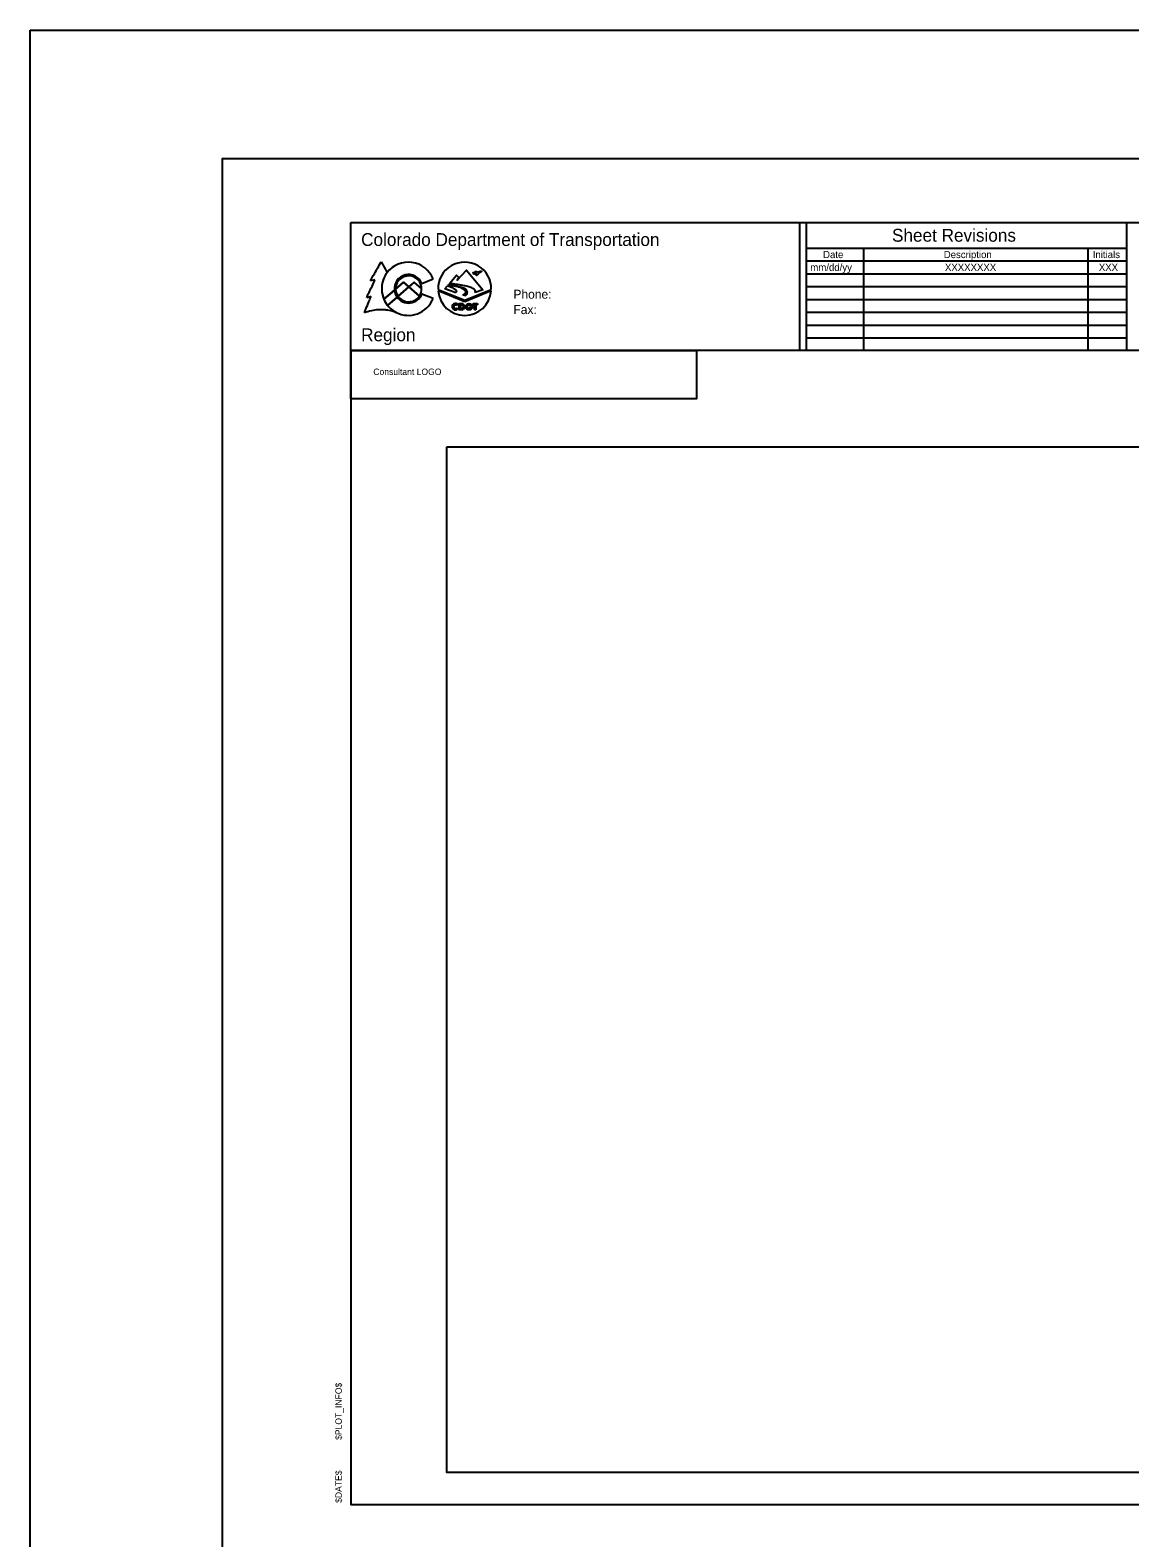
# Model space of a CAD drawing. Extents: x 0 to 3, y 0 to 2.
# Drawn here: x 0 to 0.715, y 1.02 to 2 of the extents above; entities that cross this region are included whole.
import ezdxf

# ---------------------------------------------------------------- set-up
doc = ezdxf.new("R2010")
doc.units = 0
for name, color, linetype in [('DRAFT_Information-No Plot', 7, 'Continuous'), ('SHEET_Lines', 7, 'Continuous'), ('SHEET_North Arrow', 7, 'Continuous'), ('SHEET_Plot Boundary', 7, 'Continuous'), ('SHEET_Text-Border Info', 7, 'Continuous')]:
    doc.layers.add(name, color=color, linetype=linetype)

msp = doc.modelspace()

# ---------------------------------------------------------------- linework, layer by layer
at = {"layer": 'DRAFT_Information-No Plot'}
msp.add_line((0.20833, 1.79167), (0.20833, 1.79167), dxfattribs=at)
msp.add_lwpolyline([(0.27083, 1.72917), (1.4375, 1.72917), (1.4375, 1.0625), (0.27083, 1.0625)], close=True, dxfattribs=at)
at = {"layer": 'SHEET_Lines'}
for p, q in [((0.20833, 1.79167), (0.20833, 1.875)), ((0.20833, 1.875), (1.5, 1.875)), ((0.5, 1.875), (0.5, 1.79167)), ((0.50417, 1.875), (0.50417, 1.79167)), ((0.7125, 1.875), (0.7125, 1.79167)), ((0.50417, 1.85833), (0.7125, 1.85833)), ((0.54167, 1.79167), (0.54167, 1.85833)), ((0.6875, 1.79167), (0.6875, 1.85833)), ((0.50417, 1.85), (0.7125, 1.85)), ((0.50417, 1.84167), (0.7125, 1.84167)), ((0.50417, 1.83333), (0.7125, 1.83333)), ((0.50417, 1.825), (0.7125, 1.825)), ((0.50417, 1.81667), (0.7125, 1.81667)), ((0.50417, 1.80833), (0.7125, 1.80833)), ((0.50417, 1.8), (0.7125, 1.8))]:
    msp.add_line(p, q, dxfattribs=at)
for points in [[(2.95833, 0.08333), (0.125, 0.08333), (0.125, 1.91667), (2.95833, 1.91667)], [(0.20833, 1.79167), (0.43293, 1.79167), (0.43293, 1.76025), (0.20833, 1.76025)]]:
    msp.add_lwpolyline(points, close=True, dxfattribs=at)
msp.add_lwpolyline([(1.1375, 1.79167), (0.20833, 1.79167), (0.20833, 1.04167), (1.5, 1.04167), (1.5, 1.79167), (1.275, 1.79167)], dxfattribs=at)
at = {"layer": 'SHEET_Plot Boundary'}
for p, q in [((0.22801, 1.8493), (0.232, 1.84245)), ((0.22395, 1.83769), (0.22115, 1.83706)), ((0.24264, 1.83614), (0.23747, 1.83166)), ((0.23747, 1.83161), (0.24264, 1.83609)), ((0.2461, 1.83313), (0.23903, 1.827)), ((0.23903, 1.827), (0.2461, 1.83313)), ((0.2461, 1.83313), (0.24264, 1.83614)), ((0.24264, 1.83609), (0.2461, 1.83308)), ((0.24955, 1.83613), (0.2461, 1.83313)), ((0.2461, 1.83308), (0.24955, 1.83608)), ((0.25295, 1.82719), (0.2461, 1.83313)), ((0.2461, 1.83313), (0.25295, 1.82719)), ((0.25438, 1.83194), (0.24955, 1.83613)), ((0.24955, 1.83608), (0.25438, 1.83189)), ((0.2545, 1.83542), (0.26182, 1.83834)), ((0.26939, 1.83182), (0.27121, 1.8339)), ((0.27167, 1.83442), (0.27189, 1.83467)), ((0.29036, 1.84177), (0.28894, 1.84145)), ((0.22151, 1.82697), (0.21867, 1.82609)), ((0.22986, 1.82505), (0.23669, 1.83098)), ((0.23669, 1.83098), (0.22986, 1.82505)), ((0.2384, 1.82645), (0.23224, 1.8211)), ((0.23224, 1.8211), (0.2384, 1.82645)), ((0.26182, 1.82552), (0.25453, 1.82842)), ((0.26506, 1.83148), (0.28236, 1.82442)), ((0.28236, 1.82343), (0.26511, 1.83046)), ((0.2755, 1.82967), (0.26939, 1.83182)), ((0.28142, 1.82766), (0.28106, 1.82781)), ((0.28255, 1.82728), (0.28215, 1.82746)), ((0.28236, 1.82442), (0.29966, 1.83148)), ((0.2996, 1.83046), (0.28236, 1.82343)), ((0.27715, 1.81944), (0.27787, 1.81876)), ((0.27788, 1.82166), (0.27716, 1.82099)), ((0.28784, 1.82135), (0.28784, 1.82223)), ((0.28784, 1.82223), (0.29066, 1.82223)), ((0.2888, 1.82135), (0.28784, 1.82135)), ((0.2888, 1.81812), (0.2888, 1.82135)), ((0.2897, 1.81812), (0.2888, 1.81812)), ((0.29066, 1.82135), (0.2897, 1.82135)), ((0.2897, 1.82135), (0.2897, 1.81812)), ((0.29066, 1.82223), (0.29066, 1.82135))]:
    msp.add_line(p, q, dxfattribs=at)
msp.add_lwpolyline([(0, 2), (3, 2), (3, 0), (0, 0)], close=True, dxfattribs=at)
for points in [[(0.27243, 1.83528), (0.27713, 1.84065), (0.27848, 1.83924), (0.2775, 1.8375), (0.28344, 1.84402), (0.29416, 1.8313), (0.28907, 1.82956)], [(0.2805, 1.81812), (0.27873, 1.81812), (0.27873, 1.82223), (0.2805, 1.82223)], [(0.28027, 1.82136), (0.27966, 1.82136), (0.27966, 1.81901), (0.28027, 1.81901)]]:
    msp.add_lwpolyline(points, dxfattribs=at)
for radius in [0.00212, 0.00114]:
    msp.add_circle((0.28516, 1.82022), radius, dxfattribs=at)
for centre, radius, start, end in [((0.24574, 1.83192), 0.01731, 21.75871, 203.38863), ((0.24576, 1.83193), 0.01732, 142.59022, 242.67381), ((0.28236, 1.83192), 0.01731, 358.51701, 181.48299), ((0.24592, 1.83189), 0.00928, 22.36058, 185.62032), ((0.24592, 1.83184), 0.00845, 0.35858, 181.56098), ((0.24574, 1.83192), 0.01731, 203.38863, 242.71912), ((0.24592, 1.83189), 0.00928, 185.62032, 215.87253), ((0.24592, 1.83189), 0.00845, 181.56098, 215.37659), ((0.24574, 1.83192), 0.01731, 242.71912, 338.26838), ((0.24592, 1.83189), 0.00928, 215.87253, 338.04863), ((0.24592, 1.83189), 0.00845, 215.37659, 326.23275), ((0.24592, 1.83189), 0.00845, 326.23275, 0.35858), ((0.28236, 1.83192), 0.01731, 184.84023, 355.15977), ((0.24576, 1.83193), 0.01732, 218.67794, 242.67381), ((0.24576, 1.83193), 0.01732, 218.67794, 242.67381), ((0.27632, 1.82022), 0.00212, 42.62362, 316.67791), ((0.27632, 1.82022), 0.00114, 42.62362, 316.67791), ((0.28021, 1.82019), 0.00118, 273.22356, 86.77644), ((0.28027, 1.82018), 0.00207, 276.24904, 83.75096)]:
    msp.add_arc(centre, radius, start, end, dxfattribs=at)
for points in [[(0.22115, 1.83706), (0.22299, 1.84048), (0.22567, 1.84523), (0.22801, 1.8493)], [(0.28894, 1.84145), (0.28841, 1.84144), (0.28833, 1.84151), (0.28813, 1.84174), (0.28771, 1.84222), (0.28771, 1.84236), (0.28788, 1.84244), (0.28824, 1.84241), (0.28841, 1.84227), (0.28875, 1.84205), (0.28888, 1.84205), (0.289, 1.84205), (0.29002, 1.84242)], [(0.29002, 1.84242), (0.28944, 1.84267), (0.28921, 1.84278), (0.28905, 1.84291), (0.28912, 1.843), (0.28938, 1.8431), (0.28957, 1.84315), (0.28978, 1.84313), (0.28998, 1.84308), (0.29037, 1.84296), (0.291, 1.84275)], [(0.291, 1.84275), (0.29173, 1.84304), (0.29236, 1.84325), (0.29263, 1.84333), (0.29288, 1.84337), (0.29309, 1.84335), (0.29319, 1.84326), (0.29317, 1.84305), (0.29305, 1.84287), (0.29239, 1.84249), (0.29148, 1.84209)], [(0.21867, 1.82609), (0.21973, 1.82856), (0.22349, 1.83645), (0.22395, 1.83769)], [(0.27121, 1.8339), (0.27198, 1.83367), (0.27263, 1.83345), (0.27369, 1.83303), (0.27483, 1.83239), (0.27577, 1.83177), (0.27634, 1.83132), (0.27681, 1.83074), (0.27696, 1.83044), (0.277, 1.83023), (0.27691, 1.82985), (0.27665, 1.82963), (0.27652, 1.82954), (0.27615, 1.82944), (0.27587, 1.82953), (0.27568, 1.82961), (0.2755, 1.82967)], [(0.27189, 1.83467), (0.27644, 1.83374), (0.28038, 1.83258), (0.28205, 1.83182), (0.2831, 1.83103), (0.28379, 1.83008), (0.28343, 1.82824), (0.28255, 1.82728)], [(0.28907, 1.82956), (0.2893, 1.83017), (0.28899, 1.83114), (0.28708, 1.83241), (0.28433, 1.83333), (0.2812, 1.83401), (0.27888, 1.83442), (0.27496, 1.835), (0.27243, 1.83528)], [(0.29148, 1.84209), (0.2909, 1.84127), (0.29054, 1.84075), (0.29023, 1.84056), (0.28993, 1.84058), (0.29011, 1.8411), (0.29036, 1.84177)], [(0.21726, 1.81626), (0.21817, 1.81866), (0.22011, 1.82341), (0.22151, 1.82697)], [(0.28025, 1.83238), (0.28053, 1.83225), (0.2808, 1.8321), (0.28107, 1.83193), (0.2812, 1.83185), (0.28133, 1.83177), (0.28153, 1.83165), (0.28172, 1.83152), (0.2819, 1.83138), (0.28199, 1.83131), (0.28208, 1.83124), (0.28218, 1.83115), (0.28233, 1.831), (0.28248, 1.83083), (0.28259, 1.83066), (0.28268, 1.83052), (0.28273, 1.83042), (0.28276, 1.83032), (0.28278, 1.83026), (0.2828, 1.83018), (0.28283, 1.83008), (0.28285, 1.82994), (0.28287, 1.82965), (0.28283, 1.82936), (0.2828, 1.82922), (0.28275, 1.82908), (0.28261, 1.82882), (0.28243, 1.82858), (0.28221, 1.82836), (0.28198, 1.82815), (0.28184, 1.82802), (0.2817, 1.8279), (0.28156, 1.82778), (0.28142, 1.82766)], [(0.28215, 1.82746), (0.28269, 1.8279), (0.28327, 1.82858), (0.28348, 1.82901), (0.28336, 1.83031), (0.28317, 1.83058), (0.28275, 1.831), (0.28141, 1.83189), (0.28025, 1.83238)], [(0.23781, 1.81654), (0.23532, 1.81731), (0.23132, 1.81806), (0.22837, 1.81825), (0.22628, 1.8182), (0.22173, 1.81756), (0.21726, 1.81626)]]:
    msp.add_spline(points, degree=3, dxfattribs=at)
msp.add_open_spline([(0.28106, 1.82781), (0.28572, 1.83093), (0.27855, 1.83319), (0.27167, 1.83442)], degree=2, dxfattribs=at)

# ---------------------------------------------------------------- texts
at = {"layer": 'DRAFT_Information-No Plot'}
msp.add_text('Consultant LOGO', height=0.0041667, dxfattribs=at).set_placement((0.22297, 1.77587))
at = {"layer": 'SHEET_North Arrow'}
for s, height, p in [('Colorado Department of Transportation', 0.0083333, (0.21507, 1.85972)), ('Sheet Revisions', 0.0083333, (0.56005, 1.8625)), ('Region ', 0.008333, (0.21507, 1.7978))]:
    msp.add_text(s, height=height, dxfattribs=at).set_placement(p)
at = {"layer": 'SHEET_Text-Border Info'}
for s, height, p in [('Date', 0.004667, (0.51522, 1.85183)), ('Description', 0.0046667, (0.59366, 1.85183)), ('Initials', 0.004667, (0.69049, 1.85183)), ('mm/dd/yy', 0.004667, (0.50695, 1.8435)), ('XXXXXXXX', 0.004667, (0.59444, 1.8435)), ('XXX', 0.004667, (0.69444, 1.8435)), ('Phone:', 0.005833, (0.31405, 1.82545)), ('Fax:', 0.005833, (0.31405, 1.81545))]:
    msp.add_text(s, height=height, dxfattribs=at).set_placement(p)
for s, height, p in [('$PLOT_INFO$', 0.0041667, (0.2025, 1.08367)), ('$PLOT_INFO$', 0.0041667, (0.2025, 1.08367)), ('$DATE$', 0.004167, (0.2025, 1.04273)), ('$DATE$', 0.004167, (0.2025, 1.04273))]:
    msp.add_text(s, height=height, rotation=90, dxfattribs=at).set_placement(p)

doc.saveas('drawing.dxf')
